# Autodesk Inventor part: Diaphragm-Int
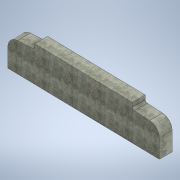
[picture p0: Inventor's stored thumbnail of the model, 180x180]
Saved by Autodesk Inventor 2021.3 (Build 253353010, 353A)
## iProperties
Created: 2021-10
Part Number: Diaphragm-Int
Material: Concrete, Precast
Document SubType Name: Modeling
Designer: u1426
Density: 2.40731 g/cm^3
Appearance: Smooth Precast Structural
Author: u1426
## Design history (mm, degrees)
sketch "Sketch1"
  geometry: L1 (-762, 1295.4)-(-762, 1261.45); L2 (-726.164, 1223.417)-(-419.726, 1205.177); L3 (-228.6, 1002.336)-(-228.6, 635); L4 (-3225.8, 697.992)-(-3225.8, 1065.328); L5 (-2692.4, 1324.442)-(-2692.4, 1358.392); L6 (-2728.236, 1286.409)-(-3034.674, 1268.169); L7 (-3225.8, 697.992)-(-228.6, 635); L8 (-3302, 1358.392)-(-3302, 215.392); L9 (-152.4, 1295.4)-(-152.4, 152.4); L10 (-2692.4, 1358.392)-(-3302, 1358.392); L11 (-762, 1295.4)-(-152.4, 1295.4); L12 (-3302, 215.392)-(-4872.129, 215.392); L13 (-152.4, 152.4)-(-1248.139, 152.4); L14 (-2692.4, 1358.392)-(-2692.4, 1383.792); L15 (-2692.4, 1383.792)-(-762, 1343.221); L16 (-762, 1343.221)-(-762, 1295.4); A1 r 203.2 centre (-431.8, 1002.336) between (-228.6, 1002.336) and (-419.726, 1205.177); A2 r 38.1 centre (-723.9, 1261.45) between (-762, 1261.45) and (-726.164, 1223.417); A3 r 203.2 centre (-3022.6, 1065.328) between (-3034.674, 1268.169) and (-3225.8, 1065.328); A4 r 38.1 centre (-2730.5, 1324.442) between (-2728.236, 1286.409) and (-2692.4, 1324.442); 5 further points
  constraints: 32 end point, 8 point on circle, 8 point on line, 8 tangent, 5 vertical, 4 centre point, 2 horizontal, 2 parallel, 2 perpendicular
  dimensions: "d12" = 69.85 distance of L1.start point (-762, 1225.55); "d16" = 31.75 vertical distance of point (-762, 1225.55) point (-228.6, 1193.8); "d23" = 203.2 radius of A1; "d24" = 38.1 radius of A2; "d68" = 533.4 horizontal distance of point (-2692.4, 1288.542) point (-3225.8, 1256.792); "d69" = 31.75 vertical distance of point (-2692.4, 1288.542) point (-3225.8, 1256.792); "d70" = 69.85 distance of point (-2692.4, 1288.542) L5.end; "d78" = 203.2 radius of A3; "d79" = 38.1 radius of A4; "d82" = 76.2 distance between parallel lines of L3 L9; "d83" = 76.2 distance between parallel lines of L4 L8; "d84" = 1143 distance of L9.start L9.end; "d85" = 1143 distance of L8.start L8.end (= d84); "d86" = 482.6 distance from line of L4.start L12 (= d87); "d87" = 482.6 distance from line of L3.end L13; "d88" = 62.992 distance between parallel lines of L13 L12 (= 0.02 x d89); "d89" = 3149.6 distance between parallel lines of L9 L8; "d90" = 25.4 distance of L5.end L14.end; "d91" = 152.4 distance from line of point (0, 0) L13; "d92" = 152.4 distance from line of point (0, 0) L9; "d93" = 533.4 distance between parallel lines of L3 L1
extrude "Extrusion9" new body sketch "Sketch1" stored distance "d94" = 254; taper "d95" = 0 deg
body "Solid4"
